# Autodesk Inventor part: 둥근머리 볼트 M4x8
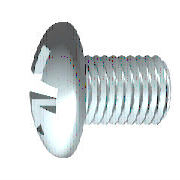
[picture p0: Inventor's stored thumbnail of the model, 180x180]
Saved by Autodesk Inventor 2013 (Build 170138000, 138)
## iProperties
Created: 2012-02
Part Number: 둥근머리 볼트 M4x8
Material: 강철, 연강
Description: 십자 오목 머리 나사
Document SubType Name: Modeling
Standard: KS B 1023
Designer: mduedu
Standards Organization: KS
Language: ko-KR
Size Designation: A  M 4 x 8 - H
Categories: <MemberInstance><Categories><Category DisplayName="조임쇠" InternalName="e4da775c-781d-43d5-af7c-5136215cf5a6" Mnemonic="FSTN"><Category DisplayName="볼트" InternalN
Density: 7.86 g/cm^3
Mass: 1.6193 g
Surface Area: 2.62082 cm^2
Volume: 0.206018 cm^3
IsCustomPart: 1
Author: mduedu
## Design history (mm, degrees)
workplane "Work Plane3"
sketch "스케치2"
  geometry: L1 (-5.374, 0)-(5.374, 0) reference; L2 (0, -5.374)-(0, 5.374) reference; L3 (0, 2.3)-(0, 0); L4 (0, 0)-(2.3, 0); L5 (0, 0)-(2.714, 2.714); L6 (0.311, 2.279)-(0.392, 0.703); L7 (2.279, 0.311)-(0.703, 0.392); L8 (0.311, -2.279)-(0.392, -0.703); L9 (2.279, -0.311)-(0.703, -0.392); L10 (-0.311, 2.279)-(-0.392, 0.703); L11 (-2.279, 0.311)-(-0.703, 0.392); L12 (-2.279, -0.311)-(-0.703, -0.392); L13 (-0.311, -2.279)-(-0.392, -0.703); A1 r 0.69 centre (0, 0) between (0.69, 0) and (0, 0.69); A2 r 2.3 centre (0, 0) between (2.3, 0) and (2.279, 0.311); A3 r 2.3 centre (0, 0) between (0.311, 2.279) and (0, 2.3); A4 r 2.3 centre (0, 0) between (2.279, 0.311) and (0.311, 2.279); A5 r 2.3 centre (0, 0) between (0, -2.3) and (0.311, -2.279); A6 r 2.3 centre (0, 0) between (0.311, -2.279) and (2.279, -0.311); A7 r 2.3 centre (0, 0) between (2.279, -0.311) and (2.3, 0); A8 r 2.3 centre (0, 0) between (-2.279, 0.311) and (-2.3, 0); A9 r 2.3 centre (0, 0) between (-0.311, 2.279) and (-2.279, 0.311); A10 r 2.3 centre (0, 0) between (0, 2.3) and (-0.311, 2.279); A11 r 2.3 centre (0, 0) between (-2.3, 0) and (-2.279, -0.311); A12 r 2.3 centre (0, 0) between (-2.279, -0.311) and (-0.311, -2.279); A13 r 2.3 centre (0, 0) between (-0.311, -2.279) and (0, -2.3); A14 r 0.805 centre (0, 0) between (0.805, 0) and (0, 0.805); A15 r 0.328 centre (0.72, 0.72) between (0.392, 0.703) and (0.703, 0.392); A16 r 0.328 centre (0.72, -0.72) between (0.703, -0.392) and (0.392, -0.703); A17 r 0.328 centre (-0.72, 0.72) between (-0.703, 0.392) and (-0.392, 0.703); A18 r 0.328 centre (-0.72, -0.72) between (-0.392, -0.703) and (-0.703, -0.392); 1 further point
  constraints: 38 point on circle, 22 end point, 19 symmetric about line, 18 centre point, 4 coincident, 3 collinear, 3 point on line, 3 tangent, 1 perpendicular, 21 other
  dimensions: "d4" = 45 deg angle of L5 L4; "d5" = 1.38 diameter of A1 (= 0.3 x SDM); "d6" = 4.6 diameter of A4 (= SDM); "d7" = 0.3115 distance from line of L6.start L3 (= 0.5 x SBR); "d14" = 1.61 diameter of A14 (= 0.35 x SDM)
extrude "슬롯" join sketch "스케치2" taper "d15" = 5 deg; stored distance "d54" = 10
revolve "절단부" stored, may be unused: angle "d56" = 90 deg
revolve "본체" stored, may be unused: angle "d18" = 90 deg
workplane "Work Plane1"
body "Solid1"
sketch "스케치1"
  geometry: L1 (8, 0)-(8, 2); L2 (8, 2)-(1.4, 2); L3 (3.962, 5.08)-(3.962, 5.08); L4 (-3.1, 0)-(-3.1, 3.729); L5 (-2.744, 2.122)-(-1.498, 1.501); L6 (-1.498, 1.501)-(-0.7, 0); L7 (-0.7, 0)-(8, 0); L8 (-5.687, 0)-(10.281, 0) reference; L9 (0, -1.016)-(0, 6.096) reference; L10 (-2.744, 2.122)-(-3.1, 2.3); L11 (-1.846, 3.839)-(-3.1, 3.729); L12 (-1.846, 3.839)-(0, 4); L13 (0, 4)-(0, 1.785); L14 (0, 1.785)-(0.971, 1.785); L15 (0.971, 1.785)-(1.4, 2); L16 (1.4, 2)-(0, 2); A1 r 6.5 centre (3.4, 0) between (-1.846, 3.839) and (-3.1, 0)
  constraints: 28 end point, 5 point on line, 4 collinear, 4 point on circle, 3 parallel, 2 perpendicular, 1 centre point, 1 horizontal, 1 tangent
  dimensions: "d1" = 4 diameter of L2 L7 (= GD); "d2" = 2.4 distance from line of L6.end L4 (= STI); "d11" = 4.6 diameter of L10.end L7 (= SDM); "d12" = 62 deg angle of L6 L7; "d13" = 26.5 deg angle of L5 L7; "d17" = 8 diameter of L12.end L7 (= KOD); "d19" = 5 deg angle of L12 L7 (= KEWI); "d20" = 3.1 distance between parallel lines of L4 L13 (= KOH); "d21" = 6.5 radius of A1 (= KR); "d23" = 3.5705 diameter of L14 L7 (= BDM); "d24" = 6.6 distance of L1.end L2.end (= GEL); "d25" = 0.42941 horizontal distance of L14.end L2.end (= GAL); "d28" = 8 distance between parallel lines of L1 L13 (= NLG)
fillet "모깎기1" dims "d29" = 1.6 (= RR)
fillet "모깎기2" dims "d16" = 0.1246 (= 0.2 x SBR)
feature "스레드" dims "d8" = 6.6 (= GEL), "d9" = 0
chamfer "모따기1" distance "d26" = 0.42941 (= -0.5 x SPD + 0.5 x GD); stored, may be unused: second distance "d27" = 0.42952 (computed from GUL), angle "d78" = 45 deg
other parameters: "GD" = 4 (= NND) [user parameter; used in 2 equation terms], "NLG" = 8 [user parameter; used in 1 equation term], "GEL" = 6.6 [user parameter; used in 2 equation terms], "KOD" = 8 [user parameter; used in 1 equation term], "KOH" = 3.1 [user parameter; used in 2 equation terms], "SDM" = 4.6 [user parameter; used in 4 equation terms], "STI" = 2.4 [user parameter; used in 1 equation term], "SBR" = 0.623 [user parameter; used in 2 equation terms], "GAL" = 0.42941 (= 0.61345 x PTC) [user parameter; used in 1 equation term], "SPD" = 3.14117 (= NND - 1.2269 x PTC) [user parameter; used in 1 equation term], "KEWI" = 5 deg [user parameter; used in 1 equation term], "d3" = -3.1 (= -KOH), "d10" = 0, "KR" = 6.5 [user parameter; used in 1 equation term], "BDM" = 3.5705 [user parameter; used in 1 equation term], "GUL" = 0.42941 (= 0.61345 x PTC) [user parameter; used in 1 equation term], "RR" = 1.6 [user parameter; used in 1 equation term], "d79" = 0, "d80" = 0, "PTC" = 0.7 [user parameter; used in 5 equation terms], "THREADDIA" = 4 [user parameter; used in 1 equation term], "TOA" = 30 deg [user parameter], "TPU" = 14.28571 (computed from PTC) [user parameter], "NND" = 4 [user parameter; used in 2 equation terms], "GD1" = 3.14117 (= THREADDIA - 1.2269 x PTC) [user parameter]
